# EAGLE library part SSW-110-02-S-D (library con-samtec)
THROUGH-HOLE .025" SQ POST SOCKET Source: Samtec SSW.pdf
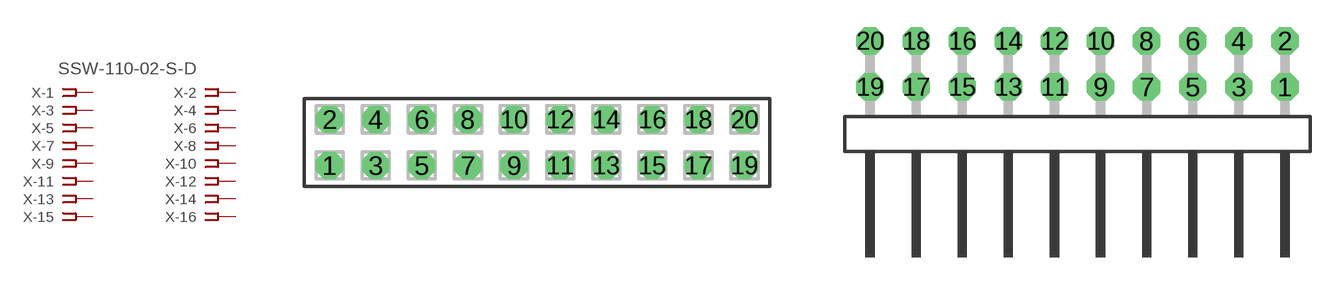
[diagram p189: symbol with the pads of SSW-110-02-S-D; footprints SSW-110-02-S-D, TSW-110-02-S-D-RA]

Designator prefix X; gates -1=FPINV -2=FPIN -3=FPIN -4=FPIN -5=FPIN -6=FPIN -7=FPIN -8=FPIN -9=FPIN -10=FPIN -11=FPIN -12=FPIN -13=FPIN -14=FPIN -15=FPIN -16=FPIN -17=FPIN -18=FPIN -19=FPIN -20=FPIN

## SSW-110-02-S-D (MPN: SSW-110-02-S-D; OC_FARNELL: unknown; OC_NEWARK: 11P9480)  [SSW-110-02-S-D]
1  -1:1  pas
2  -2:1  pas
3  -3:1  pas
4  -4:1  pas
5  -5:1  pas
6  -6:1  pas
7  -7:1  pas
8  -8:1  pas
9  -9:1  pas
10  -10:1  pas
11  -11:1  pas
12  -12:1  pas
13  -13:1  pas
14  -14:1  pas
15  -15:1  pas
16  -16:1  pas
17  -17:1  pas
18  -18:1  pas
19  -19:1  pas
20  -20:1  pas

## SSW-110-02-S-D-RA (MPN: SSW-110-02-S-D-RA; OC_FARNELL: unknown; OC_NEWARK: 11P9481)  [TSW-110-02-S-D-RA]
Pads as for SSW-110-02-S-D

## Footprint SSW-110-02-S-D (pad centres in mm)
THROUGH-HOLE .025" SQ POST SOCKET Source: Samtec SSW.pdf
drill 1 pad 1.5 octagon: 1 -11.43,-1.27; 2 -11.43,1.27; 3 -8.89,-1.27; 4 -8.89,1.27; 5 -6.35,-1.27; 6 -6.35,1.27; 7 -3.81,-1.27; 8 -3.81,1.27; 9 -1.27,-1.27; 10 -1.27,1.27; 11 1.27,-1.27; 12 1.27,1.27; 13 3.81,-1.27; 14 3.81,1.27; 15 6.35,-1.27; 16 6.35,1.27; 17 8.89,-1.27; 18 8.89,1.27; 19 11.43,-1.27; 20 11.43,1.27

## Footprint TSW-110-02-S-D-RA (pad centres in mm)
THROUGH-HOLE .025" SQ POST HEADER Source: Samtec TSW.pdf
drill 1 pad 1.5 octagon: 1 11.43,1.524; 2 11.43,4.064; 3 8.89,1.524; 4 8.89,4.064; 5 6.35,1.524; 6 6.35,4.064; 7 3.81,1.524; 8 3.81,4.064; 9 1.27,1.524; 10 1.27,4.064; 11 -1.27,1.524; 12 -1.27,4.064; 13 -3.81,1.524; 14 -3.81,4.064; 15 -6.35,1.524; 16 -6.35,4.064; 17 -8.89,1.524; 18 -8.89,4.064; 19 -11.43,1.524; 20 -11.43,4.064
